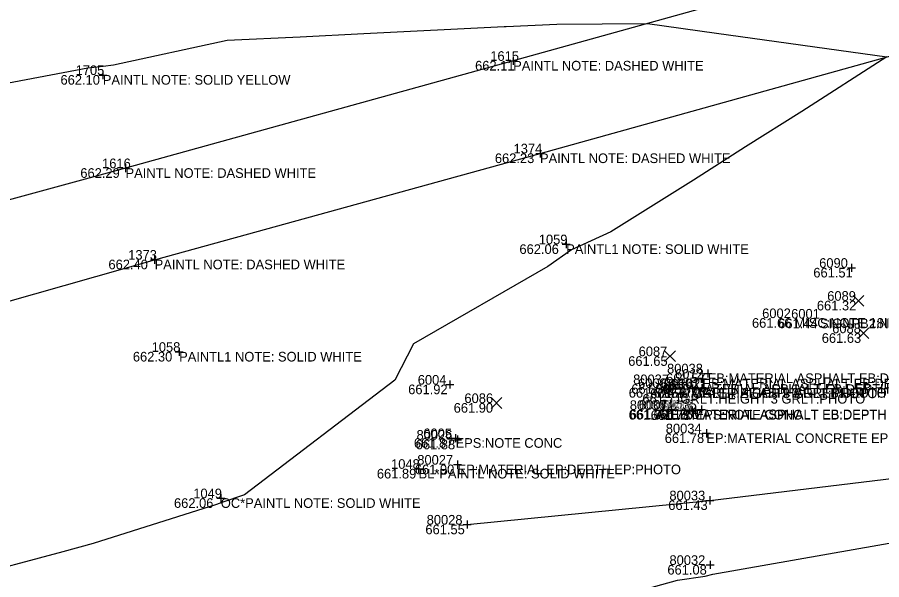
# Model space of a CAD drawing. Extents: x 2129350 to 2137777, y 657588 to 659885.
# Drawn here: x 2131820.1 to 2131927.7, y 658271.9 to 658341.9 of the extents above; entities that cross this region are included whole.
import ezdxf

# ---------------------------------------------------------------- set-up
doc = ezdxf.new("R2010")
doc.units = 0
for name, color, linetype in [('DT_X_Contour_Minor', 7, 'Continuous'), ('PV_X_COP', 7, 'Continuous'), ('SV_X_Random_Point', 7, 'Continuous'), ('SV_X_Shot_Marker', 7, 'Continuous'), ('SV_X_Text_Comment', 7, 'Continuous'), ('SV_X_Text_Elevation', 7, 'Continuous'), ('SV_X_Text_Name', 7, 'Continuous')]:
    doc.layers.add(name, color=color, linetype=linetype)

msp = doc.modelspace()

# ---------------------------------------------------------------- linework, layer by layer
at = {"layer": 'DT_X_Contour_Minor'}
for points in [[(2131808.87, 658331.83), (2131828.9, 658335.61), (2131830.79, 658335.83), (2131832.06, 658335.96), (2131846.25, 658339.03), (2131855.32, 658339.47), (2131863.26, 658339.88), (2131880.71, 658340.74), (2131880.96, 658340.75), (2131887.28, 658341.04), (2131898.57, 658341.13), (2131907.15, 658339.91), (2131928.36, 658336.97), (2131917.79, 658330.17), (2131910.77, 658325.75), (2131904.29, 658321.63), (2131894.01, 658315.19), (2131889.09, 658312.93), (2131886.16, 658310.88), (2131869.44, 658301.25), (2131867.1, 658296.72), (2131848.37, 658282.46), (2131845.58, 658281.49), (2131844.89, 658281.25), (2131829.54, 658276.4), (2131825.76, 658275.38), (2131813.32, 658272.02)], [(2131807.21, 658246.28), (2131822.78, 658249.77), (2131831.45, 658251.42), (2131840.53, 658253.76), (2131852.64, 658258.15), (2131853.93, 658258.64), (2131855.12, 658258.97), (2131858.15, 658259.81), (2131860.65, 658260.67), (2131876.31, 658264.91), (2131877.47, 658265.39), (2131877.67, 658265.69), (2131888.63, 658268.06), (2131902.29, 658271.85), (2131905.73, 658272.35), (2131906.7, 658272.57), (2131931, 658276.84)]]:
    msp.add_lwpolyline(points, dxfattribs=at)
at = {"layer": 'PV_X_COP'}
for points in [[(2132219.18, 658429.82), (2132171.04, 658416.39), (2132123.24, 658402.04), (2132074.74, 658389.73), (2132026.86, 658375.92), (2131978.48, 658362.52), (2131930.38, 658349.99), (2131881.84, 658336.47), (2131833.58, 658323.11), (2131785.59, 658310.04), (2131736.99, 658296.06), (2131689.31, 658282.66), (2131640.89, 658270.23), (2131593.04, 658256.99), (2131544.72, 658243.6), (2131496.4, 658230.41), (2131448.12, 658216.93)], [(2131451.49, 658205.21), (2131499.77, 658218.79), (2131547.68, 658232.21), (2131596.22, 658245.48), (2131644.19, 658258.61), (2131693.03, 658271.05), (2131740.4, 658284.7), (2131788.8, 658297.99), (2131837.2, 658311.72), (2131885.18, 658324.95), (2131933.63, 658338.43), (2131981.61, 658351.41), (2132029.82, 658365.04), (2132078.39, 658378.04), (2132126.27, 658391.57), (2132174.31, 658404.93), (2132222.67, 658417.74)], [(2131876.1, 658278.75), (2131906.34, 658281.77), (2131958.03, 658288), (2131975.12, 658289.49), (2132011.14, 658296.11), (2132023.11, 658297.81), (2132055.44, 658301.38), (2132113.5, 658304.52), (2132161.57, 658306.03), (2132213.08, 658306.94), (2132256.96, 658307.59), (2132314.02, 658306.01), (2132362.5, 658303.13), (2132402.04, 658304.92), (2132433.33, 658303.27)], [(2131876.1, 658278.75), (2131906.34, 658281.77), (2131958.03, 658288), (2131975.12, 658289.49), (2132011.14, 658296.11), (2132023.11, 658297.81), (2132055.44, 658301.38), (2132113.5, 658304.52), (2132161.57, 658306.03), (2132213.08, 658306.94), (2132256.96, 658307.59), (2132314.02, 658306.01), (2132362.5, 658303.13), (2132402.04, 658304.92), (2132433.33, 658303.27)]]:
    msp.add_lwpolyline(points, dxfattribs=at)
at = {"layer": 'SV_X_Random_Point'}
for p, q in [((2131924.18, 658305.94), (2131925.51, 658307.28)), ((2131924.18, 658307.28), (2131925.51, 658305.94)), ((2131924.8, 658301.9), (2131926.14, 658303.23)), ((2131924.8, 658303.23), (2131926.14, 658301.9)), ((2131900.7, 658299.04), (2131902.03, 658300.38)), ((2131900.7, 658300.38), (2131902.03, 658299.04)), ((2131879.08, 658293.21), (2131880.41, 658294.55)), ((2131879.08, 658294.55), (2131880.41, 658293.21))]:
    msp.add_line(p, q, dxfattribs=at)
at = {"layer": 'SV_X_Shot_Marker'}
for p, q in [((2131881.34, 658336.47), (2131882.34, 658336.47)), ((2131881.84, 658336.97), (2131881.84, 658335.97)), ((2131881.84, 658336.47), (2131881.84, 658336.47)), ((2131830.25, 658334.71), (2131831.25, 658334.71)), ((2131830.75, 658335.21), (2131830.75, 658334.21)), ((2131830.75, 658334.71), (2131830.75, 658334.71)), ((2131884.68, 658324.95), (2131885.68, 658324.95)), ((2131885.18, 658325.45), (2131885.18, 658324.45)), ((2131885.18, 658324.95), (2131885.18, 658324.95)), ((2131833.58, 658323.61), (2131833.58, 658322.61)), ((2131833.08, 658323.11), (2131834.08, 658323.11)), ((2131833.58, 658323.11), (2131833.58, 658323.11)), ((2131888.44, 658314.14), (2131888.44, 658313.14)), ((2131887.94, 658313.64), (2131888.94, 658313.64)), ((2131888.44, 658313.64), (2131888.44, 658313.64)), ((2131836.7, 658311.72), (2131837.7, 658311.72)), ((2131837.2, 658312.22), (2131837.2, 658311.22)), ((2131837.2, 658311.72), (2131837.2, 658311.72)), ((2131923.46, 658310.71), (2131924.46, 658310.71)), ((2131923.96, 658311.21), (2131923.96, 658310.21)), ((2131923.96, 658310.71), (2131923.96, 658310.71)), ((2131839.75, 658300.25), (2131840.75, 658300.25)), ((2131840.25, 658300.75), (2131840.25, 658299.75)), ((2131840.25, 658300.25), (2131840.25, 658300.25)), ((2131906.07, 658298.07), (2131906.07, 658297.07)), ((2131873.96, 658296.67), (2131873.96, 658295.67)), ((2131901.84, 658296.73), (2131901.84, 658295.73)), ((2131904.92, 658296.9), (2131905.92, 658296.9)), ((2131905.42, 658297.4), (2131905.42, 658296.4)), ((2131905.42, 658296.9), (2131905.42, 658296.9)), ((2131905.57, 658297.57), (2131906.57, 658297.57)), ((2131906.07, 658297.57), (2131906.07, 658297.57)), ((2131873.46, 658296.17), (2131874.46, 658296.17)), ((2131873.96, 658296.17), (2131873.96, 658296.17)), ((2131900.93, 658295.75), (2131901.93, 658295.75)), ((2131901.34, 658296.23), (2131902.34, 658296.23)), ((2131901.43, 658296.25), (2131901.43, 658295.25)), ((2131901.43, 658295.75), (2131901.43, 658295.75)), ((2131901.84, 658296.23), (2131901.84, 658296.23)), ((2131902.67, 658295.51), (2131902.67, 658294.51)), ((2131903.67, 658295.69), (2131904.67, 658295.69)), ((2131904.17, 658296.19), (2131904.17, 658295.19)), ((2131904.17, 658295.69), (2131904.17, 658295.69)), ((2131904.84, 658295.74), (2131905.84, 658295.74)), ((2131905.34, 658296.24), (2131905.34, 658295.24)), ((2131905.34, 658295.74), (2131905.34, 658295.74)), ((2131902.17, 658295.01), (2131903.17, 658295.01)), ((2131902.67, 658295.01), (2131902.67, 658295.01)), ((2131901.49, 658293.57), (2131901.49, 658292.57)), ((2131901.49, 658293.52), (2131901.49, 658292.52)), ((2131904.14, 658293.47), (2131904.14, 658292.47)), ((2131904.56, 658293.54), (2131904.56, 658292.54)), ((2131905.27, 658293.59), (2131905.27, 658292.59)), ((2131900.99, 658293.07), (2131901.99, 658293.07)), ((2131900.99, 658293.02), (2131901.99, 658293.02)), ((2131901.49, 658293.07), (2131901.49, 658293.07)), ((2131901.49, 658293.02), (2131901.49, 658293.02)), ((2131903.64, 658292.97), (2131904.64, 658292.97)), ((2131904.06, 658293.04), (2131905.06, 658293.04)), ((2131904.14, 658292.97), (2131904.14, 658292.97)), ((2131904.56, 658293.04), (2131904.56, 658293.04)), ((2131904.77, 658293.09), (2131905.77, 658293.09)), ((2131905.27, 658293.09), (2131905.27, 658293.09)), ((2131905.39, 658290.11), (2131906.39, 658290.11)), ((2131905.89, 658290.61), (2131905.89, 658289.61)), ((2131905.89, 658290.11), (2131905.89, 658290.11)), ((2131874.17, 658289.51), (2131875.17, 658289.51)), ((2131874.4, 658289.32), (2131875.4, 658289.32)), ((2131874.67, 658290.01), (2131874.67, 658289.01)), ((2131874.67, 658289.51), (2131874.67, 658289.51)), ((2131874.9, 658289.82), (2131874.9, 658288.82)), ((2131874.9, 658289.32), (2131874.9, 658289.32)), ((2131870.06, 658286.19), (2131870.06, 658285.19)), ((2131874.41, 658286.21), (2131875.41, 658286.21)), ((2131874.91, 658286.71), (2131874.91, 658285.71)), ((2131874.91, 658286.21), (2131874.91, 658286.21)), ((2131869.56, 658285.69), (2131870.56, 658285.69)), ((2131870.06, 658285.69), (2131870.06, 658285.69)), ((2131844.94, 658282.03), (2131845.94, 658282.03)), ((2131845.44, 658282.53), (2131845.44, 658281.53)), ((2131845.44, 658282.03), (2131845.44, 658282.03)), ((2131905.84, 658281.77), (2131906.84, 658281.77)), ((2131906.34, 658282.27), (2131906.34, 658281.27)), ((2131906.34, 658281.77), (2131906.34, 658281.77)), ((2131875.6, 658278.75), (2131876.6, 658278.75)), ((2131876.1, 658279.25), (2131876.1, 658278.25)), ((2131876.1, 658278.75), (2131876.1, 658278.75)), ((2131906.35, 658274.23), (2131906.35, 658273.23)), ((2131905.85, 658273.73), (2131906.85, 658273.73)), ((2131906.35, 658273.73), (2131906.35, 658273.73))]:
    msp.add_line(p, q, dxfattribs=at)

# ---------------------------------------------------------------- texts
at = {"layer": 'SV_X_Text_Comment'}
for s, p in [('PAINTL NOTE: DASHED WHITE', (2131881.84, 658335.27)), ('PAINTL NOTE: SOLID YELLOW', (2131830.75, 658333.51)), ('PAINTL NOTE: DASHED WHITE', (2131885.18, 658323.75)), ('PAINTL NOTE: DASHED WHITE', (2131833.58, 658321.91)), ('PAINTL1 NOTE: SOLID WHITE', (2131888.44, 658312.44)), ('PAINTL NOTE: DASHED WHITE', (2131837.2, 658310.53)), ('MISC:NOTE 18IN FLAT ROUND CONC WITH 6IN METAL BASE MISC:DEPTH MISC:PHOTO', (2131916.85, 658303.25)), ('SIGNPB2:NOTE1 EXIT 159 SIGNPB2:NOTE2 SIGNPB2:NOTE3 SIGNPB2:PHOTO SIGNPB2:WI', (2131920.03, 658303.19)), ('PAINTL1 NOTE: SOLID WHITE', (2131840.25, 658299.05)), ('EB:MATERIAL ASPHALT EB:DEPTH EB:PHOTO', (2131905.42, 658295.7)), ('EB:MATERIAL ASPHALT EB:DEPTH EB:PHOTO', (2131906.07, 658296.37)), ('EB:MATERIAL ASPHALT EB:DEPTH EB:PHOTO', (2131901.43, 658294.55)), ('EB:MATERIAL ASPHALT EB:DEPTH EB:PHOTO', (2131901.84, 658295.03)), ('GRLT:HEIGHT 3 GRLT:PHOTO', (2131904.17, 658294.49)), ('GRLT:HEIGHT 3 GRLT:PHOTO', (2131905.34, 658294.54)), ('GRLT:HEIGHT 3 GRLT:PHOTO', (2131902.67, 658293.81)), ('EB:MATERIAL ASPHALT EB:DEPTH EB:PHOTO', (2131901.49, 658291.87)), ('EB:MATERIAL ASPHALT EB:DEPTH EB:PHOTO', (2131901.49, 658291.82)), ('EPS:NOTE CONC', (2131904.56, 658291.83)), ('EP:MATERIAL CONCRETE EP:DEPTH EP:PHOTO', (2131905.89, 658288.91)), ('EPS:NOTE CONC', (2131874.67, 658288.31)), ('EP:MATERIAL EP:DEPTH EP:PHOTO', (2131874.91, 658285.02)), ('BL*PAINTL NOTE: SOLID WHITE', (2131870.06, 658284.49)), ('OC*PAINTL NOTE: SOLID WHITE', (2131845.44, 658280.83))]:
    msp.add_text(s, height=1.2, dxfattribs=at).set_placement(p)
at = {"layer": 'SV_X_Text_Elevation'}
for s, p in [('662.11', (2131877.1, 658335.27)), ('662.10', (2131825.48, 658333.51)), ('662.23', (2131879.56, 658323.75)), ('662.29', (2131827.95, 658321.91)), ('662.06', (2131882.62, 658312.44)), ('662.40', (2131831.45, 658310.53)), ('661.51', (2131919.21, 658309.51)), ('661.32', (2131919.65, 658305.41)), ('661.66', (2131911.57, 658303.25)), ('661.44', (2131914.84, 658303.19)), ('661.63', (2131920.26, 658301.37)), ('662.30', (2131834.49, 658299.05)), ('661.65', (2131896.16, 658298.51)), ('661.62', (2131900.22, 658295.7)), ('661.57', (2131900.88, 658296.37)), ('661.92', (2131868.77, 658294.98)), ('661.62', (2131896.23, 658294.55)), ('661.50', (2131896.55, 658295.03)), ('661.70', (2131898.9, 658294.49)), ('661.71', (2131900.61, 658294.54)), ('661.71', (2131897.93, 658293.81)), ('661.90', (2131874.43, 658292.68)), ('661.70', (2131896.22, 658291.82)), ('661.72', (2131896.34, 658291.87)), ('661.78', (2131898.96, 658291.77)), ('661.76', (2131899.31, 658291.83)), ('661.76', (2131900.03, 658291.89)), ('661.78', (2131900.71, 658288.91)), ('661.87', (2131869.48, 658288.31)), ('661.88', (2131869.71, 658288.12)), ('661.90', (2131869.6, 658285.02)), ('661.89', (2131864.87, 658284.49)), ('662.06', (2131839.61, 658280.83)), ('661.43', (2131901.15, 658280.57)), ('661.55', (2131870.91, 658277.55)), ('661.08', (2131901.04, 658272.53))]:
    msp.add_text(s, height=1.2, dxfattribs=at).set_placement(p)
at = {"layer": 'SV_X_Text_Name'}
for s, p in [('1615', (2131878.99, 658336.47)), ('1705', (2131827.36, 658334.71)), ('1374', (2131881.89, 658324.95)), ('1616', (2131830.66, 658323.11)), ('1059', (2131885.03, 658313.64)), ('1373', (2131833.91, 658311.72)), ('6090', (2131919.94, 658310.71)), ('6089', (2131920.94, 658306.61)), ('6002', (2131912.84, 658304.45)), ('6001', (2131916.45, 658304.39)), ('6088', (2131921.56, 658302.57)), ('1058', (2131836.83, 658300.25)), ('6087', (2131897.46, 658299.71)), ('80038', (2131901, 658297.57)), ('6012', (2131902, 658296.9)), ('6004', (2131869.96, 658296.17)), ('80037', (2131896.78, 658296.23)), ('6008', (2131897.4, 658295.75)), ('6010', (2131900.64, 658295.69)), ('6011', (2131902.34, 658295.74)), ('6009', (2131898.64, 658295.01)), ('6086', (2131875.77, 658293.88)), ('80036', (2131896.36, 658293.02)), ('6007', (2131897.48, 658293.07)), ('80035', (2131900.22, 658293.09)), ('6006', (2131900.46, 658293.04)), ('6013', (2131900.71, 658292.97)), ('80034', (2131900.84, 658290.11)), ('80026', (2131869.81, 658289.32)), ('6005', (2131870.65, 658289.51)), ('1048', (2131866.64, 658285.69)), ('80027', (2131869.9, 658286.21)), ('1049', (2131842.01, 658282.03)), ('80033', (2131901.29, 658281.77)), ('80028', (2131871.07, 658278.75)), ('80032', (2131901.3, 658273.73))]:
    msp.add_text(s, height=1.2, dxfattribs=at).set_placement(p)

doc.saveas('drawing.dxf')
